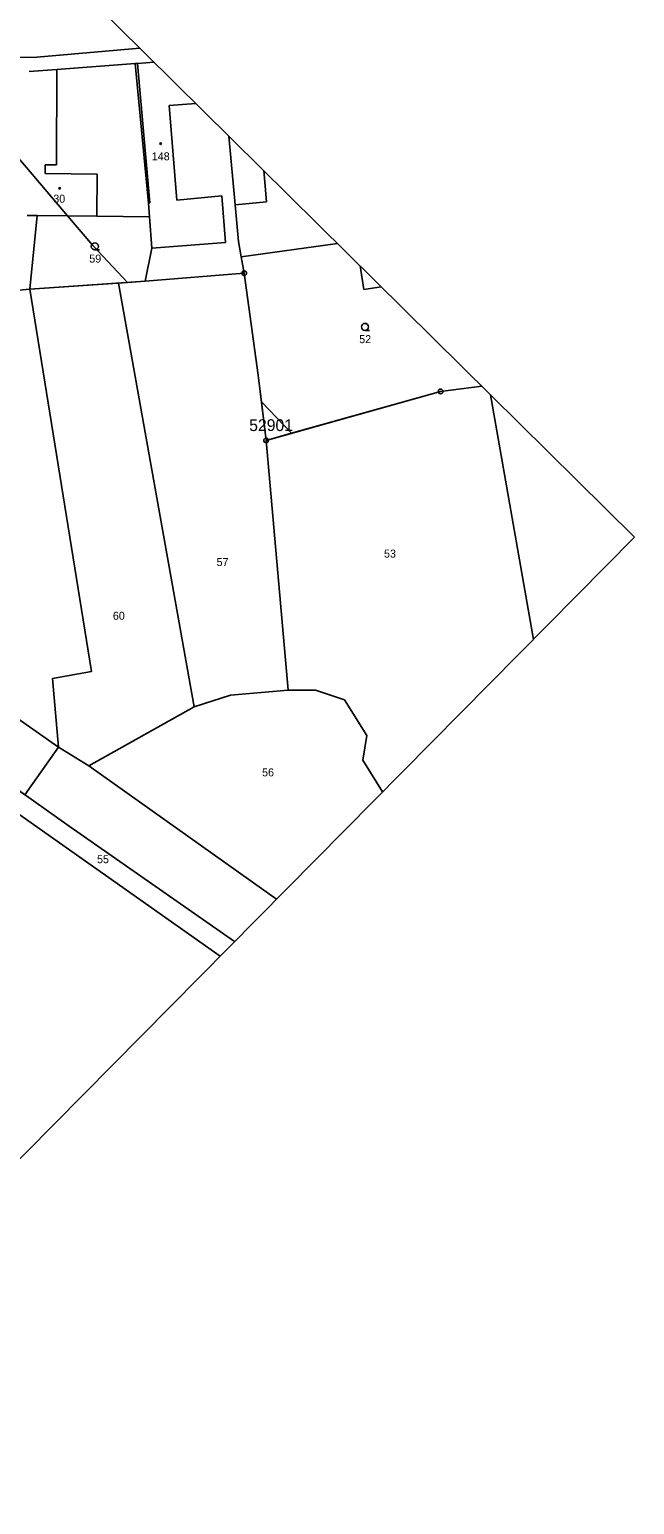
# Model space of a CAD drawing. Extents: x -777175 to -776673, y -1110537 to -1110036.
# Drawn here: x -776801.4 to -776672.9, y -1110537.2 to -1110223.9 of the extents above; entities that cross this region are included whole.
import ezdxf

# ---------------------------------------------------------------- set-up
doc = ezdxf.new("R2010")
doc.units = 0
for name, color, linetype in [('BPEJ', 7, 'Continuous'), ('Katastr_HRANICE DRÁHY', 7, 'Continuous'), ('Katastr_Hranice parcel', 7, 'Continuous'), ('Katastr_Parcelní čísla', 7, 'Continuous'), ('Katastr_pozemek SŽDC_šrafy', 7, 'Continuous'), ('Katastr_Slučkované čáry', 7, 'Continuous'), ('Katastr_Značky kultur', 7, 'Continuous')]:
    doc.layers.add(name, color=color, linetype=linetype)

msp = doc.modelspace()

# ---------------------------------------------------------------- linework, layer by layer
at = {"layer": 'BPEJ'}
for points in [[(-776852.23, -1110181.54), (-776851.73, -1110182.33), (-776845.13, -1110192.18), (-776842.54, -1110196.21), (-776837.7, -1110203.74), (-776836.65, -1110205.62), (-776829.07, -1110219.13), (-776827.66, -1110221.2), (-776826.66, -1110222.65), (-776822.05, -1110229.41), (-776821.58, -1110229.97), (-776818.14, -1110234.08), (-776814.62, -1110238.29), (-776805.87, -1110248.74), (-776802.05, -1110253.25), (-776793.36, -1110263.5)], [(-776793.36, -1110263.5), (-776788.02, -1110269.8), (-776780.63, -1110277.66)], [(-776780.63, -1110277.66), (-776801.34, -1110279.1), (-776814.49, -1110280.25), (-776823.89, -1110281.93), (-776826.29, -1110267.5), (-776831.4, -1110267.85), (-776830.95, -1110273.53), (-776856.55, -1110275.29), (-776856.32, -1110281.19), (-776854.31, -1110299.08), (-776849.62, -1110338.22), (-776894.76, -1110305.65), (-776896.59, -1110304.32), (-776903.91, -1110299.01), (-776906.52, -1110296.78), (-776914.36, -1110290.06), (-776923.15, -1110282.87), (-776931.82, -1110275.9)], [(-776752.19, -1110303.01), (-776752.89, -1110297.34), (-776755.83, -1110275.7), (-776776.85, -1110277.4), (-776780.63, -1110277.66)], [(-776705.36, -1110299.69), (-776714.14, -1110300.8), (-776745.76, -1110309.67)], [(-776745.76, -1110309.67), (-776751.19, -1110311.2), (-776752.19, -1110303.01)], [(-776752.19, -1110303.01), (-776745.76, -1110309.67)]]:
    msp.add_lwpolyline(points, dxfattribs=at)
at = {"layer": 'Defpoints'}
for p, q in [((-776672.94, -1110331.74), (-776971.6, -1110036.44)), ((-776876.14, -1110537.25), (-776672.94, -1110331.74))]:
    msp.add_line(p, q, dxfattribs=at)
at = {"layer": 'Katastr_HRANICE DRÁHY'}
for points in [[(-776757.91, -1110417.68), (-776792.98, -1110393.16), (-776846.61, -1110355.09), (-776904.52, -1110315.47), (-776922.51, -1110314.75), (-776940.41, -1110317.34)], [(-776849.62, -1110338.22), (-776813.64, -1110363.55), (-776795.25, -1110376.34), (-776788.84, -1110380.33), (-776748.99, -1110408.66)]]:
    msp.add_lwpolyline(points, dxfattribs=at)
at = {"layer": 'Katastr_Hranice parcel'}
msp.add_line((-776766.43, -1110367.83), (-776782.5, -1110277.79), dxfattribs=at)
for points in [[(-776799.9, -1110229.78), (-776777.97, -1110227.9)], [(-776830.22, -1110230.05), (-776799.9, -1110229.78)], [(-776779.02, -1110231.14), (-776795.61, -1110232.41)], [(-776778.51, -1110231.13), (-776779.02, -1110231.14)], [(-776779.02, -1110231.14), (-776776.18, -1110260.79)], [(-776778.51, -1110231.13), (-776774.98, -1110230.85)], [(-776801.53, -1110232.8), (-776795.61, -1110232.41)], [(-776759.09, -1110246.56), (-776757.74, -1110261.17)], [(-776775.96, -1110263.73), (-776776.18, -1110260.79)], [(-776757.04, -1110268.94), (-776757.74, -1110261.17)], [(-776799.81, -1110263.42), (-776801.9, -1110263.39)], [(-776801.34, -1110279.1), (-776799.81, -1110263.42)], [(-776787.15, -1110263.58), (-776799.81, -1110263.42)], [(-776775.96, -1110263.73), (-776787.15, -1110263.58)], [(-776775.96, -1110263.73), (-776775.44, -1110270.36)], [(-776756.46, -1110272.21), (-776757.04, -1110268.94)], [(-776776.85, -1110277.4), (-776775.44, -1110270.36)], [(-776756.46, -1110272.21), (-776736.03, -1110269.37)], [(-776755.83, -1110275.7), (-776756.46, -1110272.21)], [(-776730.4, -1110279.14), (-776731.19, -1110274.15)], [(-776776.85, -1110277.4), (-776801.34, -1110279.1)], [(-776755.83, -1110275.7), (-776776.85, -1110277.4)], [(-776752.89, -1110297.34), (-776755.83, -1110275.7)], [(-776801.34, -1110279.1), (-776814.49, -1110280.25)], [(-776795.25, -1110376.34), (-776796.53, -1110361.81), (-776788.29, -1110360.31), (-776801.34, -1110279.1)], [(-776730.4, -1110279.14), (-776726.73, -1110278.56)], [(-776751.19, -1110311.2), (-776752.89, -1110297.34)], [(-776705.36, -1110299.69), (-776714.14, -1110300.8)], [(-776714.14, -1110300.8), (-776751.19, -1110311.2)], [(-776694.41, -1110353.46), (-776703.54, -1110301.49)], [(-776726.46, -1110385.87), (-776730.62, -1110379.11), (-776729.8, -1110373.88), (-776734.55, -1110366.33), (-776740.71, -1110364.29), (-776746.53, -1110364.29), (-776751.19, -1110311.2)], [(-776848.72, -1110358.87), (-776760.96, -1110420.76)], [(-776746.53, -1110364.29), (-776758.73, -1110365.29), (-776766.43, -1110367.83), (-776788.84, -1110380.33)]]:
    msp.add_lwpolyline(points, dxfattribs=at)
at = {"layer": 'Katastr_pozemek SŽDC_šrafy'}
msp.add_lwpolyline([(-776939.92, -1110317.27), (-776922.51, -1110314.75), (-776904.52, -1110315.47), (-776846.61, -1110355.09), (-776802.43, -1110386.46), (-776795.25, -1110376.34), (-776813.64, -1110363.55), (-776849.21, -1110338.51)], dxfattribs=at)
at = {"layer": 'Katastr_Slučkované čáry'}
for points in [[(-776778.51, -1110231.13), (-776775.88, -1110260.76)], [(-776795.61, -1110232.41), (-776795.71, -1110252.68)], [(-776771.77, -1110240.07), (-776766.11, -1110239.62)], [(-776771.77, -1110240.07), (-776770.17, -1110260.2)], [(-776798.13, -1110254.47), (-776798.12, -1110252.66)], [(-776798.12, -1110252.66), (-776795.71, -1110252.68)], [(-776787.03, -1110254.61), (-776798.13, -1110254.47)], [(-776787.15, -1110263.58), (-776787.03, -1110254.61)], [(-776751.69, -1110253.88), (-776751.07, -1110260.55)], [(-776760.58, -1110259.26), (-776770.17, -1110260.2)], [(-776759.81, -1110269.15), (-776760.58, -1110259.26)], [(-776776.18, -1110260.79), (-776775.88, -1110260.76)], [(-776751.07, -1110260.55), (-776757.74, -1110261.17)], [(-776775.44, -1110270.36), (-776759.81, -1110269.15)]]:
    msp.add_lwpolyline(points, dxfattribs=at)
at = {"layer": 'Katastr_Značky kultur'}
for p, q in [((-776787.56, -1110270.73), (-776786.56, -1110270.73)), ((-776755.88, -1110275.7), (-776755.78, -1110275.7)), ((-776730.19, -1110287.84), (-776729.19, -1110287.84)), ((-776714.19, -1110300.8), (-776714.09, -1110300.8)), ((-776751.24, -1110311.2), (-776751.14, -1110311.2))]:
    msp.add_line(p, q, dxfattribs=at)
for centre, radius in [((-776773.57, -1110248.17), 0.175), ((-776795.04, -1110257.66), 0.175), ((-776787.56, -1110269.98), 0.75), ((-776755.83, -1110275.7), 0.499), ((-776730.19, -1110287.09), 0.75), ((-776714.14, -1110300.8), 0.499), ((-776751.19, -1110311.2), 0.499)]:
    msp.add_circle(centre, radius, dxfattribs=at)

# ---------------------------------------------------------------- texts
at = {"layer": 'BPEJ'}
msp.add_text('52901', height=2.5, dxfattribs=at).set_placement((-776754.77, -1110309.21))
at = {"layer": 'Katastr_Parcelní čísla'}
for s, p in [('148', (-776775.46, -1110251.7)), ('30', (-776796.38, -1110260.7)), ('59', (-776788.74, -1110273.43)), ('52', (-776731.4, -1110290.54)), ('53', (-776726.14, -1110336.1)), ('57', (-776761.7, -1110337.88)), ('60', (-776783.73, -1110349.3)), ('56', (-776752.04, -1110382.57)), ('55', (-776787.09, -1110401.01))]:
    msp.add_text(s, height=1.7, dxfattribs=at).set_placement(p)

doc.saveas('drawing.dxf')
